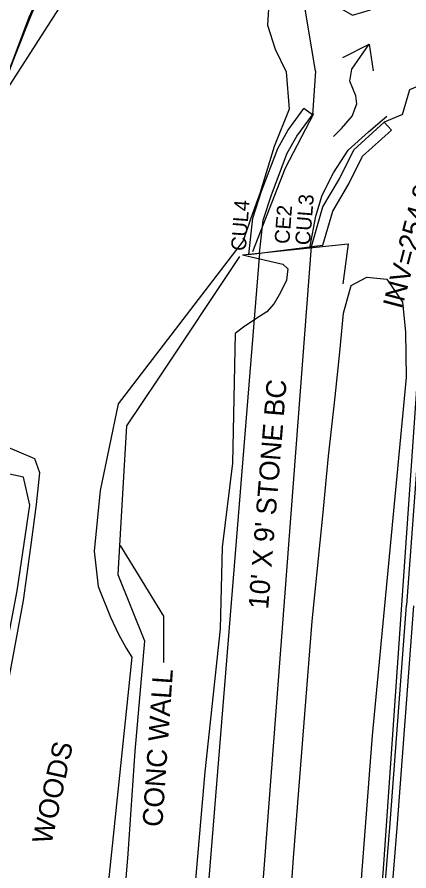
# Model space of a CAD drawing. Extents: x 2100323 to 2109811, y 740376 to 749755.
# Drawn here: x 2105513.8 to 2105592.6, y 742859.7 to 743031.4 of the extents above; entities that cross this region are included whole.
import ezdxf

# ---------------------------------------------------------------- set-up
doc = ezdxf.new("R2010")
doc.units = 0
for name, color, linetype in [('Exist Building', 7, 'Continuous'), ('Exist Building Leader', 7, 'Continuous'), ('Exist Building Text', 7, 'Continuous'), ('Exist Guardrail', 7, 'Continuous'), ('Exist Hydro Jurisdictional Stream or Body of Water', 7, 'Continuous'), ('Exist Hydro Stream or Body of Water', 7, 'Continuous'), ('Exist Other Culture Fence Line', 7, 'Continuous'), ('Exist Right of Way Line', 7, 'Continuous'), ('Exist Roads Curbs', 7, 'Continuous'), ('Exist Roads EOP Other', 7, 'Continuous'), ('Exist Structure Major Box Culvert or Tunnel Topo', 7, 'Continuous'), ('Exist Structure Major Box Culvert or Tunnel Topo Text', 7, 'Continuous'), ('Exist Structure Major Deck Tunnel Box Culvert Text', 7, 'Continuous'), ('Exist Structure Minor Head and End Wall', 7, 'Continuous'), ('Exist Structure Minor Pipes HDPE 18 Inch Invert', 7, 'Continuous'), ('Exist Survey Centerline', 7, 'Continuous'), ('Exist Vegetation Woods Line', 7, 'Continuous'), ('Exist Vegetation Woods Line Text', 7, 'Continuous')]:
    doc.layers.add(name, color=color, linetype=linetype)

msp = doc.modelspace()

# ---------------------------------------------------------------- linework, layer by layer
at = {"layer": 'Exist Building'}
for points in [[(2105573.45, 743011.94), (2105567.71, 743001.01), (2105561.18, 742984.2)], [(2105572.77, 742985.36), (2105573.92, 742991.35), (2105575.13, 742995.6), (2105577.46, 743000.12), (2105580.42, 743004.67), (2105584.45, 743008.33), (2105588.17, 743011.46)], [(2105558.54, 742983.23), (2105542.16, 742958.58), (2105535.86, 742949.2), (2105534.81, 742932.08), (2105534.08, 742919.31), (2105539.47, 742905.92), (2105537.52, 742883.74), (2105536.13, 742863.11), (2105534.35, 742841.85), (2105533.32, 742827.56), (2105522.56, 742828.59), (2105520.76, 742803.41), (2105520.65, 742800.81), (2105519.11, 742780.87), (2105518.99, 742778.38), (2105516.61, 742753.26), (2105527.37, 742752.23), (2105525.2, 742723.96), (2105523.37, 742697.86), (2105521.32, 742673.34), (2105518.92, 742640.24), (2105516.54, 742610.05), (2105515.43, 742584.56)]]:
    msp.add_lwpolyline(points, dxfattribs=at)
at = {"layer": 'Exist Building Leader'}
msp.add_lwpolyline([(2105534.53, 742925.11), (2105543.25, 742910.92), (2105543.25, 742901.6)], dxfattribs=at)
at = {"layer": 'Exist Guardrail'}
msp.add_lwpolyline([(2105498.96, 742781.56), (2105497.84, 742797.26), (2105503.77, 742859.21), (2105506.38, 742876.62), (2105513.86, 742915.99), (2105516.38, 742933.24), (2105515.15, 742938.89), (2105509.09, 742940.14)], dxfattribs=at)
at = {"layer": 'Exist Hydro Jurisdictional Stream or Body of Water'}
for p, q in [((2105573.84, 743020.52), (2105573.19, 743011.75)), ((2105591.33, 743011.85), (2105587.63, 743010.27))]:
    msp.add_line(p, q, dxfattribs=at)
for points in [[(2105573.84, 743020.52), (2105570.9, 743038.39), (2105579.05, 743033.08), (2105581.25, 743031.83), (2105584.85, 743032.9), (2105586.88, 743039.64), (2105606.16, 743069.08)], [(2105591.33, 743011.85), (2105592.75, 743016.84), (2105598.24, 743019.11), (2105602.58, 743033.35), (2105611.61, 743051.58)]]:
    msp.add_lwpolyline(points, dxfattribs=at)
at = {"layer": 'Exist Hydro Stream or Body of Water'}
for points in [[(2105577.41, 743007.37), (2105579.03, 743009.02), (2105581.21, 743011.5), (2105582.16, 743013.96), (2105581.91, 743015.61), (2105580.72, 743018.53), (2105581.13, 743020.91), (2105584.58, 743025.96)], [(2105579.3, 743023.26), (2105584.58, 743025.96), (2105585.39, 743020.6)]]:
    msp.add_lwpolyline(points, dxfattribs=at)
at = {"layer": 'Exist Other Culture Fence Line'}
msp.add_lwpolyline([(2105558.62, 742506.4), (2105565.72, 742583.51), (2105577.76, 742738.47), (2105587.46, 742860.1), (2105595.44, 742974.93), (2105672, 742969.83), (2105709.69, 742967.73)], dxfattribs=at)
at = {"layer": 'Exist Right of Way Line'}
msp.add_arc((2105890.68, 742878.29), 404.3, 148.3169, 159.9562, dxfattribs=at)
at = {"layer": 'Exist Roads Curbs'}
for points in [[(2105623.36, 742971.57), (2105596.61, 742973.66), (2105592.1, 742913.09)], [(2105562.89, 742539.41), (2105563.46, 742544.41), (2105566.01, 742573.1), (2105568.92, 742610.39), (2105572.91, 742662.45), (2105575.9, 742703.99), (2105579.11, 742745.87), (2105582.58, 742789.5), (2105585.54, 742828.69), (2105588.73, 742868.42), (2105592.1, 742913.09)]]:
    msp.add_lwpolyline(points, dxfattribs=at)
at = {"layer": 'Exist Roads EOP Other'}
for points in [[(2105528.3, 743058.34), (2105516.18, 743031.31), (2105505.72, 743003.49), (2105495.36, 742974.98), (2105486.86, 742951.46)], [(2105559.17, 742983.58), (2105580.4, 742985.81), (2105579.32, 742977.77)], [(2105559.17, 742983.58), (2105567.26, 742981.75), (2105568.25, 742980.77), (2105567.97, 742978.52), (2105566.81, 742975.99), (2105565.54, 742973.79), (2105564.03, 742972.1), (2105561.8, 742970.69), (2105559.37, 742969.04), (2105557.67, 742967.78), (2105557.17, 742941.7), (2105555.06, 742924.8), (2105554.64, 742908.39), (2105551.59, 742879.57), (2105548.89, 742848.6), (2105547.18, 742815.89), (2105545, 742789.93), (2105546, 742776.07)], [(2105564.98, 742539.26), (2105564.96, 742544.27), (2105567.5, 742572.98), (2105570.41, 742610.27), (2105574.41, 742662.34), (2105577.39, 742703.87), (2105580.61, 742745.75), (2105584.08, 742789.38), (2105587.04, 742828.57), (2105590.23, 742868.3), (2105593.6, 742912.98)]]:
    msp.add_lwpolyline(points, dxfattribs=at)
at = {"layer": 'Exist Structure Major Box Culvert or Tunnel Topo'}
for p, q in [((2105535.55, 742489.71), (2105572.99, 742985.25)), ((2105562.58, 742983.93), (2105522.63, 742491.25))]:
    msp.add_line(p, q, dxfattribs=at)
at = {"layer": 'Exist Structure Minor Head and End Wall'}
for p, q in [((2105573.19, 743011.75), (2105571.5, 743013.01)), ((2105587.63, 743010.27), (2105589.07, 743008.68)), ((2105560.43, 742983.66), (2105575.31, 742985.55)), ((2105572.99, 742985.25), (2105575.31, 742985.55)), ((2105560.43, 742983.66), (2105562.58, 742983.93))]:
    msp.add_line(p, q, dxfattribs=at)
for points in [[(2105560.43, 742983.66), (2105561.22, 742990.98), (2105562.99, 742996.4), (2105566.22, 743004.98), (2105568.29, 743008.61), (2105571.5, 743013.01)], [(2105562.58, 742983.93), (2105563.3, 742990.54), (2105564.97, 742995.69), (2105568.12, 743004.07), (2105570.05, 743007.44), (2105573.19, 743011.75)], [(2105572.99, 742985.25), (2105575.31, 742993.27), (2105578.64, 742998.89), (2105581.5, 743004.72), (2105587.63, 743010.27)], [(2105575.31, 742985.55), (2105577.3, 742992.41), (2105580.53, 742997.87), (2105583.25, 743003.41), (2105589.07, 743008.68)]]:
    msp.add_lwpolyline(points, dxfattribs=at)
at = {"layer": 'Exist Survey Centerline'}
msp.add_arc((2105890.68, 742878.29), 434.3, 148.3169, 159.9562, dxfattribs=at)
at = {"layer": 'Exist Vegetation Woods Line'}
for points in [[(2105505.36, 743006.83), (2105537.52, 743056.97)], [(2105564.49, 743035.32), (2105564.19, 743029.82), (2105565.71, 743024.99), (2105567.92, 743020.41), (2105568.53, 743012.91), (2105565.53, 743005.39), (2105562.71, 742996.15), (2105560.75, 742990.77), (2105559.27, 742986.38), (2105534.16, 742953.63), (2105530.51, 742936.22), (2105529.34, 742924), (2105530.11, 742916.9), (2105532.65, 742910.72), (2105534.23, 742907.29), (2105535.76, 742904.5), (2105536.93, 742902.65), (2105529.87, 742835.16)], [(2105568.69, 742851.72), (2105569.38, 742862.29), (2105573.17, 742909.87), (2105575.31, 742931.12), (2105576.43, 742943.08), (2105577.79, 742955.06), (2105578.74, 742963.99), (2105579.46, 742971.87), (2105580.99, 742977.42), (2105584.16, 742979.07), (2105588.17, 742978.73), (2105591.34, 742974.1), (2105591.88, 742968.11), (2105592.02, 742958.94), (2105585.2, 742886.9), (2105579.51, 742812.55)], [(2105511.16, 742892.7), (2105515.16, 742914.03), (2105516.62, 742924.81), (2105517.76, 742933.35), (2105518.4, 742939.72), (2105517.43, 742942.55), (2105511.1, 742945.22)]]:
    msp.add_lwpolyline(points, dxfattribs=at)

# ---------------------------------------------------------------- texts
at = {"layer": 'Exist Building Text'}
msp.add_text('CONC WALL', height=4, rotation=86.1062, dxfattribs=at).set_placement((2105543.02, 742868.42))
at = {"layer": 'Exist Structure Major Box Culvert or Tunnel Topo Text'}
msp.add_text("10' X 9' STONE BC", height=4, rotation=85.3643, dxfattribs=at).set_placement((2105564.3, 742912.19))
at = {"layer": 'Exist Structure Major Deck Tunnel Box Culvert Text'}
for s, rotation, p in [('CUL3', 85.4716, (2105572.7, 742985.45)), ('CUL4', 85.812, (2105559.81, 742984.29)), ('CE2', 85.8843, (2105568.56, 742985.71))]:
    msp.add_text(s, height=3, rotation=rotation, dxfattribs=at).set_placement(p)
at = {"layer": 'Exist Structure Minor Pipes HDPE 18 Inch Invert'}
msp.add_text("INV=254.81'", height=4, rotation=75.3009, dxfattribs=at).set_placement((2105591.17, 742972.53))
at = {"layer": 'Exist Vegetation Woods Line Text'}
msp.add_text('WOODS', height=4, rotation=77.8136, dxfattribs=at).set_placement((2105520.73, 742864.85))

doc.saveas('drawing.dxf')
